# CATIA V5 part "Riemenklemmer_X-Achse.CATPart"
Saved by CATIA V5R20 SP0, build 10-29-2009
Part number: Riemenklemmer_X-Achse
Bounding box of the stored display mesh (mm): x -12 to 12, y -6 to 12, z -11 to 2
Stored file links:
  C:\Users\Andi\Desktop\Offene Projekte\Plasmacutter\Riemenklemmer_X-Achse.CATPart
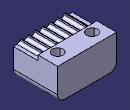
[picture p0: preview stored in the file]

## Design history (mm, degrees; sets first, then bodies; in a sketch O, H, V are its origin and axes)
Body1 (main body)
  Sketch1 on yz-plane, origin (0, 0, 0), H (0, 1, 0), V (0, 0, 1)
    line L1 (-6, 0) -> (4, 0)
    line L2 (4, 0) -> (4, 2)
    line L3 (4, 2) -> (12, 2)
    line L4 (12, 2) -> (12, -11)
    line L5 (12, -11) -> (-6, -11)
    line L6 (-6, -11) -> (-6, 0)
    distance L5 L3 = 13
    distance L3 L1 = 2
    distance L6 L4 = 18
    distance V L4 = 12
    distance L2 L6 = 10
    horizontal: L1 H, L3 H, L5 H
    vertical: L2 V, L4 V, L6 V
    coincidence: L1 H
  Pad1: profile Sketch1, direction (1, 0, 0), length 12, mirrored extent
  Sketch2 on zx-plane, origin (0, 0, 0), H (-1, 0, 0), V (0, 0, 1)
    arc A1 centre (-1.5, 1.13) radius 1.13 from (-1.5, 0) to (-0.3951, 0.8929) ccw
    point P1 (-1.5, 1.13)
    line L1 (-0.1018, 1.13) -> (0.1018, 1.13)
    line L2 (1.5, 0) -> (-1.5, 0)
    arc A2 centre (-0.1018, 0.83) radius 0.3 from (-0.3951, 0.8929) to (-0.1018, 1.13) cw
    arc A3 centre (1.5, 1.13) radius 1.13 from (0.3951, 0.8929) to (1.5, 0) ccw
    arc A4 centre (0.1018, 0.83) radius 0.3 from (0.3951, 0.8929) to (0.1018, 1.13) ccw
    distance P1 V = 1.5
    distance L1 H = 1.13
    radius A2 = 0.3
    tangency: A1 H, L2 A1, A2 L1, A2 A1, A4 A3, A4 L1
    horizontal: L1 H
    coincidence: P1 L1, O L2
    symmetry: A4 A2 V, A3 A1 V
  Pad2: profile Sketch2, direction (0, 1, 0), up to face of Pad1 from Sketch1.L2, opposite side up to face of Pad1 from Sketch1.L6
  RectPattern1: of Pad2, direction 1 instances 1, spacing 20, along zx-plane, direction 2 instances 7, spacing 3, along zx-plane, Nv 4
  Sketch3 on face of Pad1 from Sketch1.L5, origin (0.3261, 11.1206, -11), H (1, 0, 0), V (0, -1, 0)
    point P1 (-7.3261, 4.1206)
    reference intersected line E1 through (0, 11.1206) direction (1, 0) from zx-plane
    reference projected line E2 (-12.3261, 17.1206) -> (-12.3261, -0.8794) from edge [start face of Pad1 | face of Pad1 from Sketch1.L5]
    distance P1 E1 = 7
    distance P1 E2 = 5
  Hole1: placed by Sketch3, at (-7, 7, -11) direction (0, 0, 1), diameter 4.3, through (limit type 6), counterbore diameter 8, counterbore depth 4.5
  Mirror1: of Hole1, about yz-plane
  Fillet1: radius 3, on edge [start face of Pad1 | face of Pad1 from Sketch1.L5]; edge [face of Pad1 from Sketch1.L5 | end face of Pad1]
